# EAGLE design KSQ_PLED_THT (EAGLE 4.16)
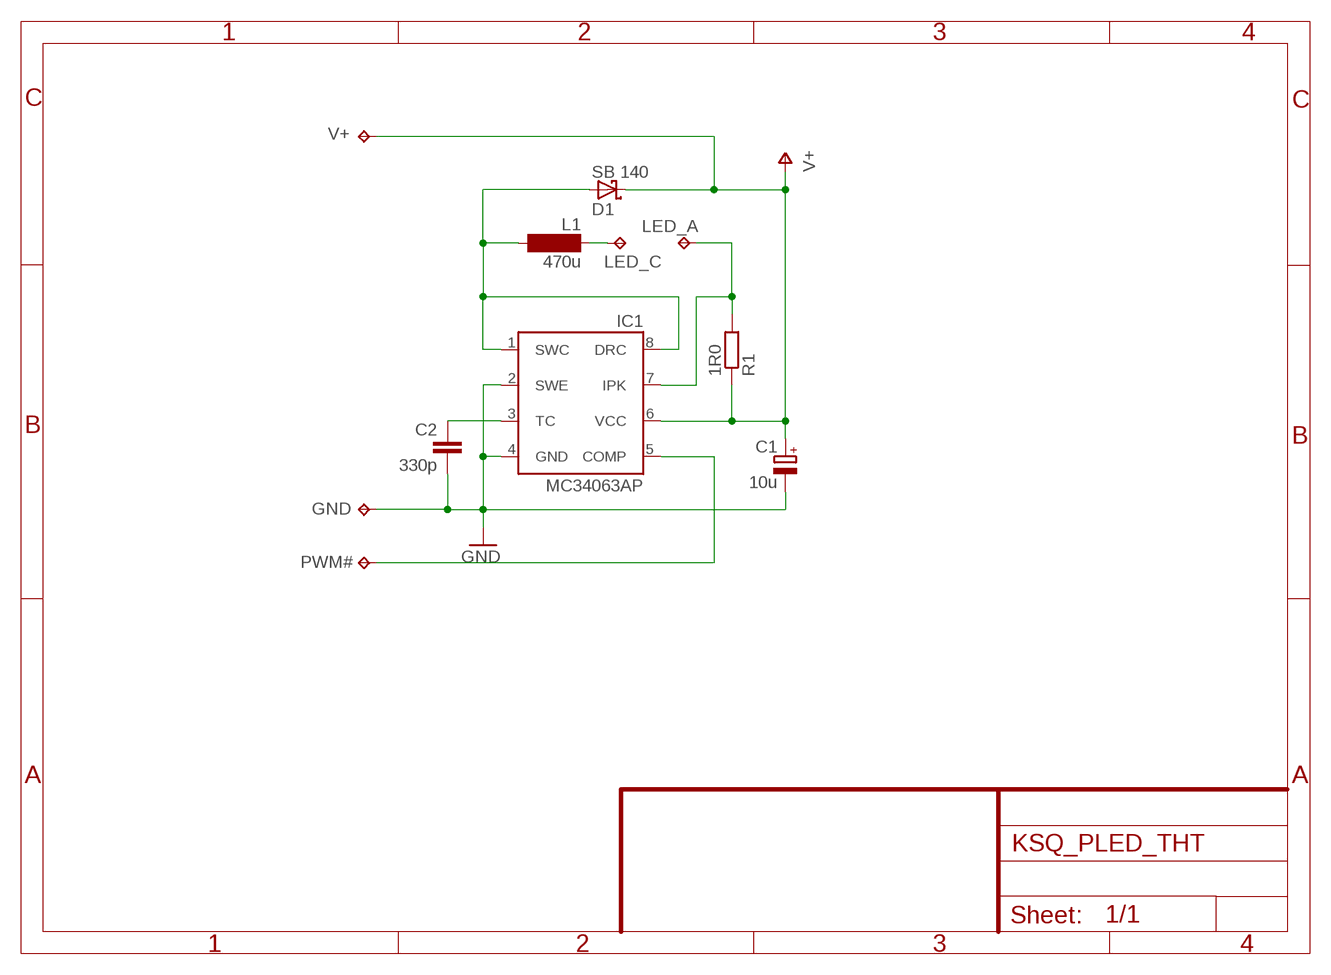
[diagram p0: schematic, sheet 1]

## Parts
C1  10u  CPOL-EUE2.5-6  [E2,5-6]
C2  330p  C-EU025-024X044  [C025-024X044]
D1  SB 140  SCHOTTKY-DIODEF126Z12  [F126Z12]
GND  TPPAD1-20  [P1-20]
IC1  MC34063AP  [DIL-08]
L1  470u  SD12-1000  [SD12_1000]
LED_A  TPPAD1-20  [P1-20]
LED_C  TPPAD1-20  [P1-20]
PWM#  TPPAD1-20  [P1-20]
R1  1R0  R-EU_0207/10  [0207/10]
V+  TPPAD1-20  [P1-20]

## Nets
GND: C1.- C2.2 GND.1(TP) IC1.2(SWE) IC1.4(GND)
N$1: D1.A IC1.1(SWC) IC1.8(DRC) L1.2
N$2: L1.1 LED_C.1(TP)
N$4: IC1.7(IPK) LED_A.1(TP) R1.2
N$7: C2.1 IC1.3(TC)
N$9: IC1.5(COMP) PWM#.1(TP)
V+: C1.+ D1.C IC1.6(VCC) R1.1 V+.1(TP)

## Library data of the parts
C1 = rcl:CPOL-EU: POLARIZED CAPACITOR, European symbol
C2 = rcl:C-EU: CAPACITOR, European symbol
D1 = diode:SCHOTTKY-DIODE: Schottky Diode
GND LED_A LED_C PWM# V+ = testpad:TP
IC1 = v-reg-3:MC34063A: 1.5A Step-Up/Down/Inverting Switching Regulator NPN Darlington Switch, Vin 3V to 40V, Current Limiter Input, adjustable Frequency up to 100kHz
L1 = inductor-neosid:SD12: INDUCTOR
R1 = rcl:R-EU_: RESISTOR, European symbol

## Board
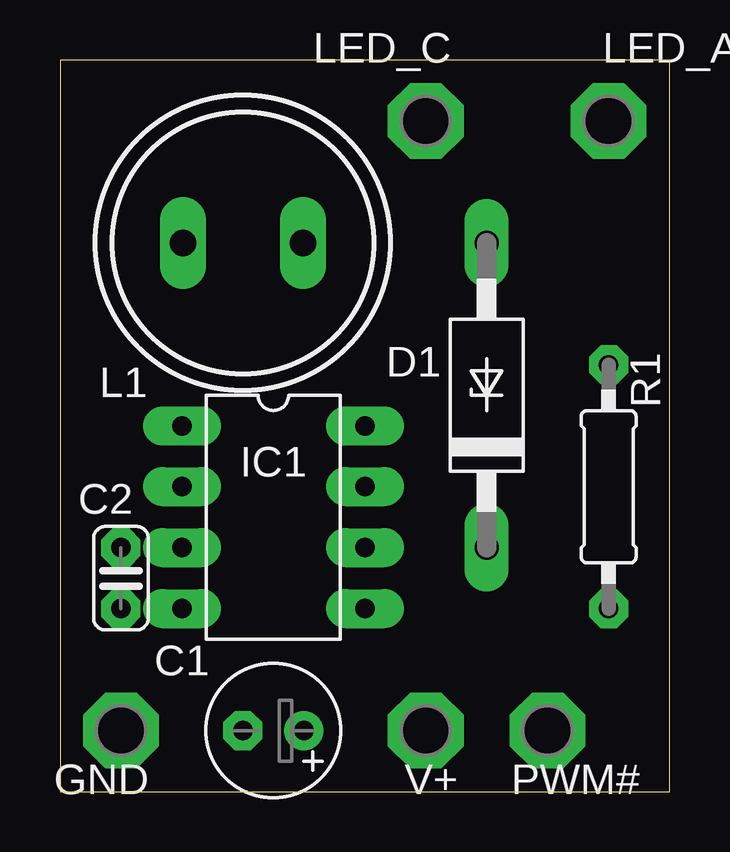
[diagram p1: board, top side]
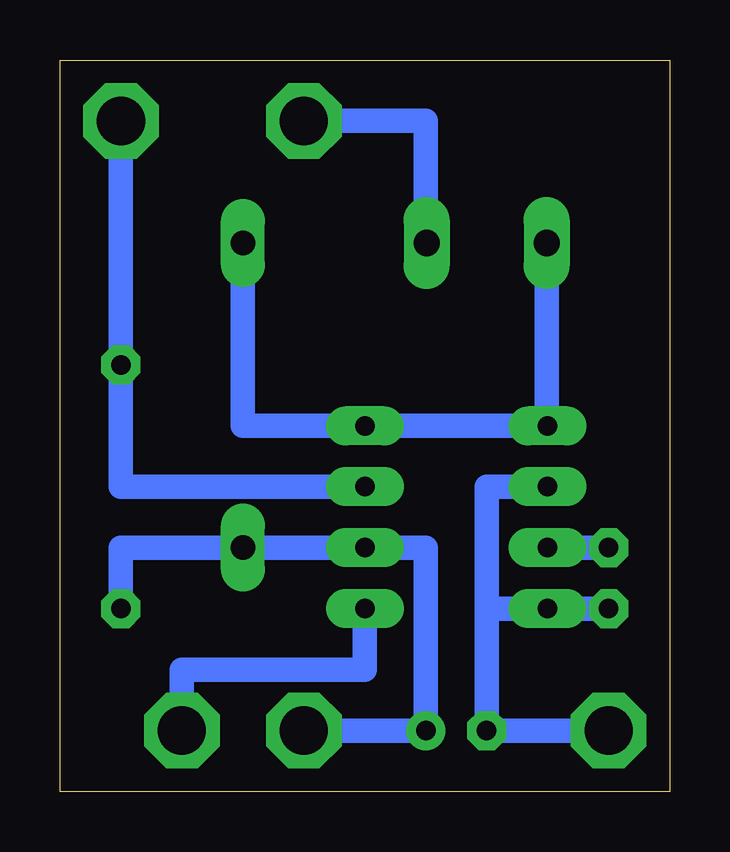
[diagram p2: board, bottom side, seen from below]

Size 25.4 x 30.48 mm. Coordinates in mm from the lower left corner, seen from the top.
Outline: 0,0 25.4,0 25.4,30.48 0,30.48 0,0
Copper layers (1*16): Top 0.035mm / dielectric 1.5mm / Bottom 0.035mm
Design rules "default": minimum track width 10mil, minimum drill 24mil, track to track 14mil, track to pad 14mil, pad to pad 14mil, via to via 14mil, smd to smd 14mil, copper to edge 40mil, drill to drill 8mil, minimum pad ring 16mil, minimum via ring 8mil, stop-mask expansion 4mil, vias tented up to drill 0mil, thermal gap 10mil

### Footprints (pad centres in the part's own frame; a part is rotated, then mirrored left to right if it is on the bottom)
E2,5-6 = drill 0.813 pad 1.6 round: + -1.27,0 | drill 0.813 pad 1.6 octagon: - 1.27,0
C025-024X044 = drill 0.813 octagon: 1 -1.27,0; 2 1.27,0
F126Z12 = drill 1.016 long: A 6.35,0; C -6.35,0
P1-20 = drill 2.007 pad 3.15 octagon: 1 0,0
DIL-08 = drill 0.813 long: 1 -3.81,-3.81; 2 -1.27,-3.81; 3 1.27,-3.81; 4 3.81,-3.81; 5 3.81,3.81; 6 1.27,3.81; 7 -1.27,3.81; 8 -3.81,3.81
SD12_1000 = drill 1.1 long: 1 -2.5,0; 2 2.5,0
0207/10 = drill 0.813 octagon: 1 -5.08,0; 2 5.08,0

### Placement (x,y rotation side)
C1  8.89,2.54 180 top
C2  2.54,8.89 270 top
D1  17.78,16.51 90 top
GND  2.54,2.54 0 top
IC1  8.89,11.43 270 top
L1  7.62,22.86 180 top
LED_A  22.86,27.94 0 top
LED_C  15.24,27.94 0 top
PWM#  20.32,2.54 0 top
R1  22.86,12.7 90 top
V+  15.24,2.54 0 top

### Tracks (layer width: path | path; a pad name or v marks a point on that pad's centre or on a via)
GND
  Bottom 1.016: GND.1 C1.- 7.62,7.62 | IC1.2 7.62,12.7 7.62,7.62 | 7.62,7.62 IC1.4 C2.2
N$1
  Bottom 0.406: IC1.1 5.12,15.28
  Bottom 1.016: 5.12,15.28 L1.2 | IC1.1 IC1.8 17.78,15.24 D1.A
N$2
  Bottom 1.016: LED_C.1 10.16,27.94 10.16,22.86 L1.1
N$4
  Bottom 1.016: IC1.7 22.86,12.7 R1.2 LED_A.1
N$7
  Bottom 1.016: C2.1 IC1.3
N$9
  Bottom 1.016: IC1.5 12.7,5.08 20.32,5.08 PWM#.1
V+
  Bottom 0.406: 11.43,10.16 IC1.6
  Bottom 1.016: 11.43,10.16 10.16,10.16 C1.+ V+.1 | IC1.6 D1.C 22.86,10.16 R1.1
